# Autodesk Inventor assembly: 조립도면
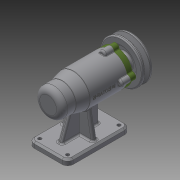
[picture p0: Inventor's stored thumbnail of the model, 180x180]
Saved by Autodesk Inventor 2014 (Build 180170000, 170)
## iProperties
Created: 2019-07
Part Number: 조립도면
Document SubType Name: Assembly
Designer: kh
Author: kh
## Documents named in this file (12)
- C:\Users\kh\Desktop\490704V1076\조립도면.iam
- C:\Users\kh\Desktop\490704V1076\본체.ipt
- C:\Users\kh\Desktop\490704V1076\V벨트풀리.ipt
- C:\Users\kh\Desktop\490704V1076\멈춤나사 M3.ipt
- C:\Users\kh\Desktop\490704V1076\베어링 6004.ipt
- C:\Users\kh\Desktop\490704V1076\베어링 51202.ipt
- C:\Users\kh\Desktop\490704V1076\볼트 M4.ipt
- C:\Users\kh\Desktop\490704V1076\어댑터슬리브.ipt
- C:\Users\kh\Desktop\490704V1076\오일 실.ipt
- C:\Users\kh\Desktop\490704V1076\축.ipt
- C:\Users\kh\Desktop\490704V1076\커버.ipt
- C:\Users\kh\Desktop\490704V1076\키 5 x 5 x 16.ipt
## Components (1 placed, 1 different names)
1. V벨트풀리:1 — Mate:21, Mate:22, Mate:23, Mate:24
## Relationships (4: Mate 4)
- Mate:21: V벨트풀리:1
- Mate:22: V벨트풀리:1
- Mate:23: V벨트풀리:1
- Mate:24: V벨트풀리:1
